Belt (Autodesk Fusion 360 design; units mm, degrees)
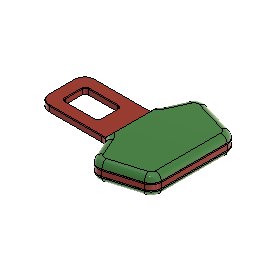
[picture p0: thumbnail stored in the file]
derived_base_feature "Derived Base Feature" bodies "seat_belt-side"
move "Move1"
move "Move2"
sketch "Sketch1" plane through (0, 0, 8) normal (0, 0, 1) x axis (-1, 0, 0)
  line L1 (-22.3557, -17.6067) -> (-22.3557, 13.9595)
  line L2 (-3.1532, -27.1019) -> (-18.7964, -22.3947)
  line L3 (6.6283, -15.8038) -> (2.8614, -24.3338)
  line L4 (36.4443, -12.8236) -> (11.2021, -12.8236)
  line L5 (41.4443, 4.1764) -> (41.4443, -7.8236)
  line L6 (11.2021, 9.1764) -> (36.4443, 9.1764)
  line L7 (2.8614, 20.6865) -> (6.6283, 12.1565)
  line L8 (-18.7964, 18.7474) -> (-3.1532, 23.4546)
  line L9 (18.5443, 2.1264) -> (18.5443, -5.7736)
  line L10 (34.0443, 3.6264) -> (20.0443, 3.6264)
  line L11 (35.5443, -5.7736) -> (35.5443, 2.1264)
  line L12 (20.0443, -7.2736) -> (34.0443, -7.2736)
  line L13 (8.4726, 9.9871) -> (8.4726, -13.6344)
  arc A1 centre (-17.3557, 13.9595) radius 5 clockwise from (-22.3557, 13.9595) to (-18.7964, 18.7474)
  arc A2 centre (-17.3557, -17.6067) radius 5 clockwise from (-18.7964, -22.3947) to (-22.3557, -17.6067)
  arc A3 centre (-1.7125, -22.314) radius 5 clockwise from (2.8614, -24.3338) to (-3.1532, -27.1019)
  arc A4 centre (11.2021, -17.8236) radius 5 clockwise from (6.6283, -15.8038) to (11.2021, -12.8236)
  arc A5 centre (36.4443, -7.8236) radius 5 clockwise from (41.4443, -7.8236) to (36.4443, -12.8236)
  arc A6 centre (36.4443, 4.1764) radius 5 clockwise from (36.4443, 9.1764) to (41.4443, 4.1764)
  arc A7 centre (11.2021, 14.1764) radius 5 clockwise from (11.2021, 9.1764) to (6.6283, 12.1565)
  arc A8 centre (-1.7125, 18.6667) radius 5 clockwise from (-3.1532, 23.4546) to (2.8614, 20.6865)
  arc A9 centre (20.0443, 2.1264) radius 1.5 clockwise from (18.5443, 2.1264) to (20.0443, 3.6264)
  arc A10 centre (34.0443, 2.1264) radius 1.5 clockwise from (34.0443, 3.6264) to (35.5443, 2.1264)
  arc A11 centre (34.0443, -5.7736) radius 1.5 clockwise from (35.5443, -5.7736) to (34.0443, -7.2736)
  arc A12 centre (20.0443, -5.7736) radius 1.5 clockwise from (20.0443, -7.2736) to (18.5443, -5.7736)
  point P38 (8.4726, -13.6344)
  point P39 (8.4726, 9.9871)
  midpoint A4 P38
  midpoint A7 P39
extrude "Extrude1" new body sketch "Sketch1" profile of A1 L1 A2 L2 A3 L3 A4 A7 L7 A8 L8 L13 along normal blind 3 bodies "seat_belt"
chamfer "Chamfer1" distance 2
fillet "Fillet1" radius 3
chamfer "Chamfer2" distance 0.3
chamfer "Chamfer3" distance 0.3
mirror "Mirror1" mirrorStitchTolerance 0.1 bodies "seat_belt (1)"
move "Move3"
named bodies: "seat_belt-side", "seat_belt", "seat_belt (1)"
